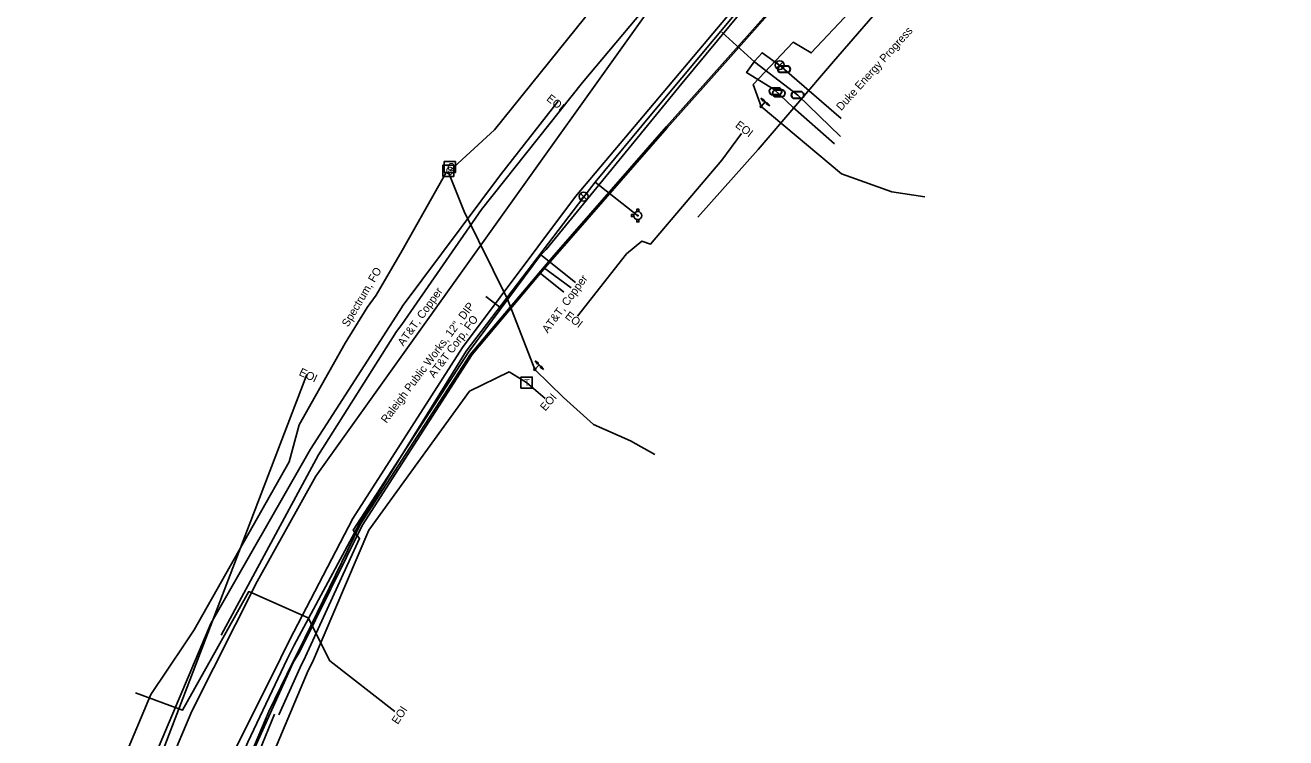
# Model space of a CAD drawing. Extents: x 2070721 to 2083340, y 729290 to 737883.
# Drawn here: x 2081411 to 2082041, y 734274 to 734630 of the extents above; entities that cross this region are included whole.
import ezdxf

# ---------------------------------------------------------------- set-up
doc = ezdxf.new("R2010")
doc.units = 0
for name, color, linetype in [('Exist Utilities Other Pole With Base Text', 7, 'Continuous'), ('Exist Utilities Other Unknown UG SUE LOS B', 7, 'Continuous'), ('Exist Utilities Power Pole Text', 7, 'Continuous'), ('Exist Utilities Power UG Cable SUE LOS B', 7, 'Continuous'), ('Exist Utilities Power UG Cable SUE LOS B Text', 7, 'Continuous'), ('Exist Utilities Telephone Pedestal CELL', 7, 'Continuous'), ('Exist Utilities Telephone Pedestal Text', 7, 'Continuous'), ('Exist Utilities Telephone UG Cable SUE LOS C', 7, 'Continuous'), ('Exist Utilities Telephone UG Cable SUE LOS C Leader', 7, 'Continuous'), ('Exist Utilities Telephone UG Cable SUE LOS C Text', 7, 'Continuous'), ('Exist Utilities Telephone UG FO SUE LOS B', 7, 'Continuous'), ('Exist Utilities Telephone UG FO SUE LOS B Text', 7, 'Continuous'), ('Exist Utilities TV Change of Service SUE CELL', 7, 'Continuous'), ('Exist Utilities TV Pedestal CELL', 7, 'Continuous'), ('Exist Utilities TV UG FO Cable SUE LOS B', 7, 'Continuous'), ('Exist Utilities TV UG FO Cable SUE LOS B Text', 7, 'Continuous'), ('Exist Utilities TV UG FO Cable SUE LOS C', 7, 'Continuous'), ('Exist Utilities Water Fire Hydrant CELL', 7, 'Continuous'), ('Exist Utilities Water Meter CELL', 7, 'Continuous'), ('Exist Utilities Water UG Line SUE LOS B', 7, 'Continuous'), ('Exist Utilities Water UG Line SUE LOS B Leader', 7, 'Continuous'), ('Exist Utilities Water UG Line SUE LOS B Text', 7, 'Continuous'), ('Exist Utilities Water Valve CELL', 7, 'Continuous')]:
    doc.layers.add(name, color=color, linetype=linetype)

msp = doc.modelspace()

# ---------------------------------------------------------------- linework, layer by layer
at = {"layer": 'Exist Utilities Other Unknown UG SUE LOS B'}
for points in [[(2081599.02, 734480.52), (2081638.91, 734537.92), (2081689.31, 734601.45), (2081739.23, 734661.21), (2081776.34, 734700.28), (2081815.77, 734743.2), (2081849.28, 734780.93), (2081877.42, 734814.37), (2081912.75, 734856.19), (2081950.81, 734928.53), (2081978.43, 734978.59)], [(2081599.1, 734489.28), (2081599.22, 734489.45), (2081648.33, 734555.35), (2081677.16, 734592.15)], [(2081686.88, 734484.58), (2081711.27, 734515.79), (2081718.94, 734522.1), (2081723.27, 734520.61), (2081758.99, 734562.68), (2081768.79, 734576.06)], [(2081503.56, 734331.04), (2081553.34, 734418.19), (2081599.1, 734489.28)], [(2081508.66, 734325.21), (2081557.42, 734415.37), (2081596.29, 734477.07), (2081599.02, 734480.52)], [(2081306.2, 733834.68), (2081331.52, 733896.97), (2081357.74, 733949.48), (2081551.49, 734455.55)], [(2081422.3, 734128.51), (2081434.71, 734162.6), (2081462.76, 734234.36), (2081499.05, 734320.38), (2081503.56, 734331.04)]]:
    msp.add_lwpolyline(points, dxfattribs=at)
at = {"layer": 'Exist Utilities Power UG Cable SUE LOS B'}
for points in [[(2081747.02, 734534.16), (2081777.19, 734567.94), (2081814.78, 734612), (2081844.33, 734646.12), (2081879.78, 734685.51), (2081910.59, 734706.71), (2081931.49, 734737.7), (2081947.42, 734760.31), (2081973.14, 734786.73), (2081997.07, 734814.98), (2082022.89, 734845.44), (2082040.83, 734835.09)], [(2081595.54, 734287.01), (2081563.06, 734312.34), (2081552.22, 734333.79), (2081522.51, 734346.94), (2081511.21, 734326.7)], [(2081511.21, 734326.7), (2081506.34, 734317.99), (2081489.43, 734287.72), (2081465.87, 734296.43)]]:
    msp.add_lwpolyline(points, dxfattribs=at)
at = {"layer": 'Exist Utilities Telephone Pedestal CELL'}
msp.add_line((2081661.3, 734451.42), (2081661.3, 734451.42), dxfattribs=at)
msp.add_lwpolyline([(2081658.57, 734448.6), (2081664.16, 734448.6), (2081664.16, 734454.19), (2081658.57, 734454.19), (2081658.57, 734448.6)], dxfattribs=at)
at = {"layer": 'Exist Utilities Telephone UG Cable SUE LOS C'}
for points in [[(2080953.21, 732796.69), (2081054.09, 733077.62), (2081111.09, 733245.57), (2081176.08, 733423.78), (2081231.97, 733580.28), (2081320.16, 733847.08), (2081418.84, 734093.09), (2081467.34, 734224.03), (2081494.06, 734287.2), (2081526.74, 734352.01), (2081556, 734404.62), (2081808.13, 734757.73), (2081845.73, 734804.26), (2081874.67, 734821.58), (2081898.66, 734810.94), (2081917.15, 734795.51)], [(2081675.15, 734515.17), (2081731.28, 734579.5), (2081761.87, 734613.73), (2081821.11, 734680.35), (2081882.55, 734750.91), (2081917.05, 734795.26)], [(2081675.44, 734514.41), (2081731.46, 734578.64), (2081762.11, 734613), (2081821.17, 734679.68), (2081882.84, 734750.34), (2081917.15, 734795.51)], [(2081671.19, 734518.01), (2081739, 734601.03), (2081786.76, 734658.83), (2081825.08, 734699.74), (2081848.94, 734723.65), (2081862.89, 734715.73), (2081883.59, 734698.93), (2081903.62, 734680.48), (2081932.44, 734654.41), (2081944.85, 734644.1)], [(2081547.42, 734317.11), (2081578.2, 734380.44), (2081633.4, 734465.71), (2081670.26, 734509.52), (2081675.15, 734515.17)], [(2081547.99, 734317.07), (2081579.24, 734380.05), (2081634.09, 734465.51), (2081670.76, 734509.17), (2081675.44, 734514.41)], [(2081550.8, 734314.52), (2081577.86, 734373.58), (2081574.68, 734377.67), (2081632.27, 734466.65), (2081668.29, 734515.1), (2081671.19, 734518.01)], [(2081554.35, 734311.73), (2081582.46, 734377.73), (2081632.84, 734447.21), (2081652.71, 734456.89)], [(2081652.71, 734456.89), (2081661.26, 734451.47), (2081670.58, 734443.46)], [(2081296.4, 733658.15), (2081287.8, 733664.8), (2081303.6, 733706.37), (2081324.3, 733763.14), (2081337.34, 733798.98), (2081373.91, 733899.45), (2081408.19, 733990.78), (2081432.67, 734050.1), (2081441.11, 734071.31), (2081457.65, 734065.9), (2081441.97, 734074.17), (2081465.76, 734134.1), (2081494.56, 734199.64), (2081510.1, 734235.63), (2081525.23, 734269.67), (2081532.48, 734287.03), (2081544.5, 734311.63), (2081547.42, 734317.11)], [(2081296.31, 733658.4), (2081289.16, 733664.06), (2081304.03, 733706.05), (2081324.8, 733762.93), (2081337.87, 733799.07), (2081374.5, 733899.39), (2081408.89, 733991.2), (2081433.1, 734049.99), (2081442.72, 734074.23), (2081467.51, 734133.17), (2081494.99, 734199.31), (2081510.48, 734235.4), (2081525.69, 734269.34), (2081544.76, 734311.53), (2081547.99, 734317.07)], [(2081537.47, 734285.43), (2081548.25, 734308.96), (2081550.8, 734314.52)], [(2081296.39, 733658.2), (2081307.45, 733685.25), (2081318.77, 733704.29), (2081345.73, 733792.08), (2081384.21, 733895.19), (2081416.52, 733988.47), (2081438.43, 734048.05), (2081472.15, 734132.3), (2081497.77, 734194.3), (2081521.27, 734233.79), (2081552.24, 734307.58), (2081554.35, 734311.73)], [(2081296.32, 733658.45), (2081292.23, 733667.87), (2081304.13, 733678.02), (2081310.51, 733703.91), (2081344.1, 733799.36), (2081380.98, 733896.99), (2081413.3, 733989.25), (2081435.43, 734048.8), (2081469.68, 734133.31), (2081498.8, 734198.46), (2081514.35, 734234.28), (2081535.34, 734285.71)]]:
    msp.add_lwpolyline(points, dxfattribs=at)
at = {"layer": 'Exist Utilities Telephone UG Cable SUE LOS C Leader'}
for p, q in [((2081668.5, 734515.35), (2081685.88, 734501.56)), ((2081669.89, 734509.05), (2081683.65, 734498.75)), ((2081668.21, 734506.12), (2081679.93, 734496.7))]:
    msp.add_line(p, q, dxfattribs=at)
at = {"layer": 'Exist Utilities Telephone UG FO SUE LOS B'}
for points in [[(2081542.88, 734322.62), (2081574.46, 734383.49), (2081629.3, 734469.05), (2081685.73, 734544.41), (2081784.03, 734661.28), (2081824.87, 734707.78), (2081827.69, 734710.71)], [(2081248.81, 733567.64), (2081281.2, 733657.22), (2081333.49, 733797.21), (2081369.06, 733900.16), (2081403.11, 733993), (2081427.18, 734053.08), (2081460.75, 734136.42), (2081485.85, 734201.8), (2081501.51, 734239.63), (2081538.45, 734313.8), (2081542.88, 734322.62)]]:
    msp.add_lwpolyline(points, dxfattribs=at)
at = {"layer": 'Exist Utilities TV Change of Service SUE CELL'}
for p, q in [((2081782.98, 734589.81), (2081778.4, 734593.63)), ((2081778.59, 734589.45), (2081780.57, 734591.82)), ((2081778.59, 734589.45), (2081778.59, 734589.45)), ((2081780.57, 734591.82), (2081782.98, 734589.81)), ((2081665.48, 734458.07), (2081667.64, 734460.27)), ((2081665.48, 734458.07), (2081665.48, 734458.07)), ((2081669.88, 734458.07), (2081665.63, 734462.25)), ((2081667.64, 734460.27), (2081669.88, 734458.07))]:
    msp.add_line(p, q, dxfattribs=at)
for points in [[(2081778.4, 734593.63), (2081780.13, 734592.63), (2081779.59, 734592.64), (2081779.69, 734592.16)], [(2081782.98, 734589.81), (2081781.24, 734590.81), (2081781.79, 734590.8), (2081781.69, 734591.28)], [(2081665.63, 734462.25), (2081667.27, 734461.11), (2081666.73, 734461.16), (2081666.79, 734460.67)], [(2081669.88, 734458.07), (2081668.23, 734459.2), (2081668.77, 734459.15), (2081668.72, 734459.64)]]:
    msp.add_lwpolyline(points, close=True, dxfattribs=at)
for centre in [(2081778.59, 734589.45), (2081665.48, 734458.07)]:
    msp.add_circle(centre, 0.517, dxfattribs=at)
at = {"layer": 'Exist Utilities TV Pedestal CELL'}
for p, q in [((2081623, 734559.19), (2081623, 734559.19)), ((2081622.23, 734557.3), (2081622.23, 734557.3))]:
    msp.add_line(p, q, dxfattribs=at)
for points in [[(2081619.45, 734554.52), (2081625, 734554.52), (2081625, 734560.07), (2081619.45, 734560.07), (2081619.45, 734554.52)], [(2081620.23, 734556.41), (2081625.78, 734556.41), (2081625.78, 734561.96), (2081620.23, 734561.96), (2081620.23, 734556.41)]]:
    msp.add_lwpolyline(points, dxfattribs=at)
at = {"layer": 'Exist Utilities TV UG FO Cable SUE LOS B'}
for points in [[(2081778.59, 734589.45), (2081774.62, 734600.43), (2081794.64, 734621.57), (2081803.63, 734616.23), (2081853.41, 734669.28), (2081872.71, 734694.38), (2081871.55, 734697.36), (2081875.65, 734699.45), (2081880.56, 734705.11), (2081892.44, 734706.39), (2081905.37, 734713.26), (2081917.92, 734727.97), (2081923.61, 734738.76)], [(2081622.95, 734557.31), (2081645.25, 734577.74), (2081708.9, 734656.89), (2081737.07, 734692.25)], [(2081621.16, 734556.51), (2081599.23, 734517.52), (2081586.14, 734495.22)], [(2081622.18, 734557.02), (2081630.2, 734537.03), (2081651.9, 734493.19), (2081665.48, 734458.07)], [(2081495.24, 734327.83), (2081542.69, 734411.91), (2081547.63, 734430.38), (2081570.62, 734471.08), (2081581.67, 734489.02), (2081586.14, 734495.22)], [(2081305.07, 733834.62), (2081318.51, 733883.96), (2081344.94, 733950.24), (2081370.6, 734023.22), (2081385.26, 734060), (2081415.18, 734152.65), (2081441.55, 734219.41), (2081473.57, 734295.5), (2081490.54, 734320.82), (2081495.24, 734327.83)]]:
    msp.add_lwpolyline(points, dxfattribs=at)
at = {"layer": 'Exist Utilities TV UG FO Cable SUE LOS C'}
for points in [[(2081778.59, 734589.45), (2081818.8, 734555.84), (2081843.88, 734546.87), (2081860.36, 734544.26)], [(2081665.48, 734458.07), (2081679.84, 734443.95), (2081694.88, 734430.56), (2081713.25, 734422.31), (2081725.44, 734415.53)]]:
    msp.add_lwpolyline(points, dxfattribs=at)
at = {"layer": 'Exist Utilities Water Fire Hydrant CELL'}
msp.add_line((2081716.95, 734534.94), (2081716.95, 734534.94), dxfattribs=at)
for points in [[(2081715.04, 734535.45), (2081713.75, 734535.45), (2081713.75, 734534.43), (2081715.04, 734534.43)], [(2081716.44, 734536.85), (2081716.44, 734538.14), (2081717.47, 734538.14), (2081717.47, 734536.83)], [(2081716.44, 734533.03), (2081716.44, 734531.74), (2081717.47, 734531.74), (2081717.47, 734533.05)]]:
    msp.add_lwpolyline(points, dxfattribs=at)
for radius in [1.98, 0.243]:
    msp.add_circle((2081716.95, 734534.94), radius, dxfattribs=at)
at = {"layer": 'Exist Utilities Water Meter CELL'}
for p, q in [((2081790.05, 734608.13), (2081790.05, 734608.13)), ((2081785.8, 734597.09), (2081785.8, 734597.09)), ((2081787.45, 734596.09), (2081787.45, 734596.09)), ((2081796.84, 734595.2), (2081796.84, 734595.2))]:
    msp.add_line(p, q, dxfattribs=at)
for points in [[(2081788.01, 734609.83), (2081792.09, 734609.83)], [(2081788.01, 734609.69), (2081792.09, 734609.69)], [(2081792.09, 734606.57), (2081787.99, 734606.57)], [(2081792.09, 734606.43), (2081787.99, 734606.43)], [(2081787.83, 734595.53), (2081783.73, 734595.53)], [(2081783.76, 734598.79), (2081787.83, 734598.79)], [(2081783.76, 734598.66), (2081787.83, 734598.66)], [(2081785.41, 734597.79), (2081789.48, 734597.79)], [(2081785.41, 734597.66), (2081789.48, 734597.66)], [(2081794.81, 734596.9), (2081798.88, 734596.9)], [(2081794.81, 734596.76), (2081798.88, 734596.76)], [(2081787.83, 734595.39), (2081783.73, 734595.39)], [(2081789.48, 734594.53), (2081785.38, 734594.53)], [(2081789.48, 734594.39), (2081785.38, 734594.39)], [(2081798.88, 734593.64), (2081794.78, 734593.64)], [(2081798.88, 734593.5), (2081794.78, 734593.5)]]:
    msp.add_lwpolyline(points, dxfattribs=at)
for centre, radius, start, end in [((2081788.74, 734608.12), 1.86, 113.17804, 245.97939), ((2081788.75, 734608.12), 1.73, 115.30093, 243.78236), ((2081791.34, 734608.13), 1.86, 293.64832, 66.30838), ((2081791.35, 734608.13), 1.73, 295.12717, 64.87283), ((2081784.49, 734597.09), 1.86, 113.17804, 245.97939), ((2081784.5, 734597.09), 1.73, 115.30093, 243.78236), ((2081786.14, 734596.09), 1.86, 113.17804, 245.97939), ((2081786.15, 734596.09), 1.73, 115.30093, 243.78236), ((2081787.09, 734597.1), 1.86, 293.64832, 66.30838), ((2081787.1, 734597.09), 1.73, 295.12717, 64.87283), ((2081788.74, 734596.09), 1.86, 293.64832, 66.30838), ((2081788.75, 734596.09), 1.73, 295.12717, 64.87283), ((2081795.54, 734595.2), 1.86, 113.17804, 245.97939), ((2081795.55, 734595.2), 1.73, 115.30093, 243.78236), ((2081798.14, 734595.2), 1.86, 293.64832, 66.30838), ((2081798.15, 734595.2), 1.73, 295.12717, 64.87283)]:
    msp.add_arc(centre, radius, start, end, dxfattribs=at)
at = {"layer": 'Exist Utilities Water UG Line SUE LOS B'}
msp.add_line((2081695.6, 734551.63), (2081716.77, 734534.98), dxfattribs=at)
for points in [[(2081545.19, 734320.14), (2081577.78, 734381.02), (2081631.24, 734467.17), (2081690.06, 734544.38), (2081695.68, 734551.66), (2081723.83, 734585.62), (2081785.29, 734659.45), (2081832.89, 734707.14)], [(2081818.27, 734574.45), (2081796.99, 734595.16), (2081775.51, 734611.69), (2081758.88, 734626.61)], [(2081815.34, 734570.79), (2081794.4, 734589.2), (2081785.08, 734597.9), (2081771.35, 734606.46), (2081775.48, 734612.29), (2081779.08, 734616.33), (2081787.98, 734610), (2081790.24, 734608), (2081818.52, 734583.55)], [(2081490.29, 734199.14), (2081491.68, 734202.17), (2081522.1, 734271.61), (2081541.68, 734313.21), (2081545.19, 734320.14)]]:
    msp.add_lwpolyline(points, dxfattribs=at)
at = {"layer": 'Exist Utilities Water UG Line SUE LOS B Leader'}
msp.add_line((2081647.98, 734489.19), (2081641.02, 734494.48), dxfattribs=at)
at = {"layer": 'Exist Utilities Water Valve CELL'}
for points in [[(2081789.43, 734611.72), (2081786.28, 734608.57), (2081787.85, 734610.15), (2081789.43, 734608.57), (2081786.28, 734611.72)], [(2081691.41, 734546.02), (2081688.26, 734542.87), (2081689.84, 734544.44), (2081691.41, 734542.87), (2081688.26, 734546.02)]]:
    msp.add_lwpolyline(points, dxfattribs=at)
for centre in [(2081787.85, 734610.15), (2081689.84, 734544.44)]:
    msp.add_circle(centre, 2.23, dxfattribs=at)

# ---------------------------------------------------------------- texts
at = {"layer": 'Exist Utilities Other Pole With Base Text'}
for rotation, p in [(321.29169, (2081670.98, 734592.84)), (322.47624, (2081765.33, 734579.52)), (322.47624, (2081680.23, 734484.19)), (335.04332, (2081547.25, 734455.32))]:
    msp.add_text('EOI', height=4, rotation=rotation, dxfattribs=at).set_placement(p)
at = {"layer": 'Exist Utilities Power Pole Text'}
msp.add_text('EOI', height=4, rotation=56.96084, dxfattribs=at).set_placement((2081596.98, 734280.28))
at = {"layer": 'Exist Utilities Power UG Cable SUE LOS B Text'}
msp.add_text('Duke Energy Progress', height=4, rotation=48.01251, dxfattribs=at).set_placement((2081818.66, 734587.13))
at = {"layer": 'Exist Utilities Telephone Pedestal CELL'}
msp.add_text('T', height=3.42, dxfattribs=at).set_placement((2081660.16, 734449.71))
at = {"layer": 'Exist Utilities Telephone Pedestal Text'}
msp.add_text('EOI', height=4, rotation=49.41631, dxfattribs=at).set_placement((2081670.72, 734436.92))
at = {"layer": 'Exist Utilities Telephone UG Cable SUE LOS C Text'}
for rotation, p in [(53.85323, (2081671.96, 734475.9)), (54.47157, (2081599.77, 734469.36))]:
    msp.add_text('AT&T, Copper', height=4, rotation=rotation, dxfattribs=at).set_placement(p)
at = {"layer": 'Exist Utilities Telephone UG FO SUE LOS B Text'}
msp.add_text('AT&T Corp, FO', height=4, rotation=53.16883, dxfattribs=at).set_placement((2081615.13, 734453.47))
at = {"layer": 'Exist Utilities TV Pedestal CELL'}
for p in [(2081620.92, 734555.3), (2081621.69, 734557.19)]:
    msp.add_text('C', height=4, dxfattribs=at).set_placement(p)
at = {"layer": 'Exist Utilities TV UG FO Cable SUE LOS B Text'}
msp.add_text('Spectrum, FO', height=4, rotation=59.40022, dxfattribs=at).set_placement((2081572.15, 734478.94))
at = {"layer": 'Exist Utilities Water UG Line SUE LOS B Text'}
msp.add_text('Raleigh Public Works, 12", DIP ', height=4, rotation=53.16319, dxfattribs=at).set_placement((2081591.38, 734430.81))

doc.saveas('drawing.dxf')
